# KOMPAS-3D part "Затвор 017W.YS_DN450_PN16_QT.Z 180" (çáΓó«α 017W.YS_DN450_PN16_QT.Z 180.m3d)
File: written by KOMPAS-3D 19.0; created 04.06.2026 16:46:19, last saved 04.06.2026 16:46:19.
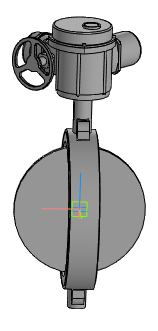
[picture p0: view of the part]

Document properties: Автор: Энергия; Полное имя файла: ..\..\..\3d для проектировщиков\017W разные\x.x Тип 017W.Y(S) Затвор дисковый поворотный межфланцевый\Затвор 017W.Y(S)_DN32-DN450_QT.Z\Затвор 017W.YS_DN450_PN16_QT.Z 180.a3d

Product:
- Part/product: Затвор 017W.YS_DN450_PN16_QT.Z 180
    Масса: 159.212

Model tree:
1. Операция без истории:1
